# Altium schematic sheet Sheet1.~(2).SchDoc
size A4
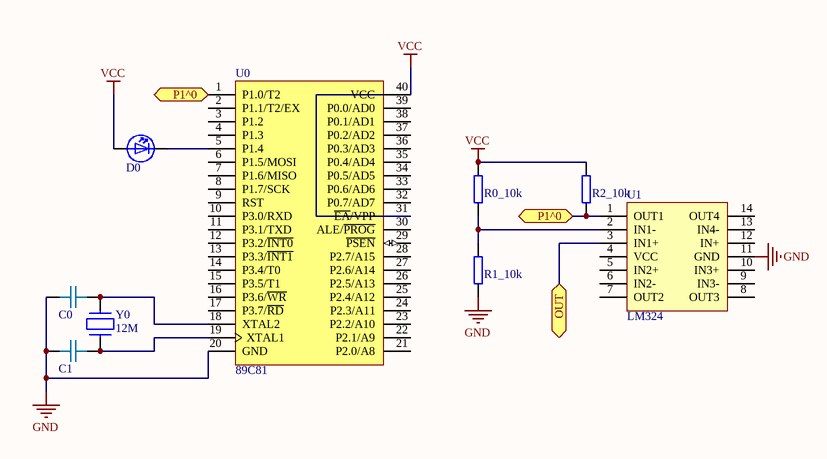
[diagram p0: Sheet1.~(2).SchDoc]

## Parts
C0  22pf  [capacitor-0.1]  (value not drawn)
C1  C_1  [capacitor-0.1]  (value not drawn)
D0  LED  [led-3]  (value not drawn)
R0_10k  RESIS  [resistor-0.4]  (value not drawn)
R1_10k  RESIS  [resistor-0.4]  (value not drawn)
R2_10k  RESIS  [resistor-0.4]  (value not drawn)
U0  89C81  [STC12C5A08S2]
U1  LM324  [DIP14]
Y0  XTAL  [Axial 0.2]  (value not drawn)

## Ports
OUT, P1^0

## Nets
GND: C0.1 C1.1 R1_10k.1 U0.20(GND) U1.11(GND)
VCC: D0.1 R0_10k.2 R2_10k.2 U0.40(VCC)
OUT: U1.3(IN1+) ; port OUT
P1^0: R2_10k.1 U0.1(P1.0/T2) U1.1(OUT1) ; port P1^0
NetC0_2: C0.2 U0.18(XTAL2) Y0.2
NetC1_2: C1.2 U0.19(XTAL1) Y0.1
NetD0_2: D0.2 U0.5(P1.4)
NetR0_10k_1: R0_10k.1 R1_10k.2 U1.2(IN1-)

Not connected (* = marked no-connect by the designer): U0 2(P1.1/T2/EX) 3(P1.2) 4(P1.3) 6(P1.5/MOSI) 7(P1.6/MISO) 8(P1.7/SCK) 9(RST) 10(P3.0/RXD) 11(P3.1/TXD) 12(P3.2/~{INT0}) 13(P3.3/~{INT1}) 14(P3.4/T0) 15(P3.5/T1) 16(P3.6/~{WR}) 17(P3.7/~{RD}) 21(P2.0/A8) 22(P2.1/A9) 23(P2.2/A10) 24(P2.3/A11) 25(P2.4/A12) 26(P2.5/A13) 27(P2.6/A14) 28(P2.7/A15) 29(~{PSEN}) 30(ALE/~{PROG}) 31(~{EA}/VPP) 32(P0.7/AD7) 33(P0.6/AD6) 34(P0.5/AD5) 35(P0.4/AD4) 36(P0.3/AD3) 37(P0.2/AD2) 38(P0.1/AD1) 39(P0.0/AD0); U1 4(VCC) 5(IN2+) 6(IN2-) 7(OUT2) 8(OUT3) 9(IN3-) 10(IN3+) 12(IN+) 13(IN4-) 14(OUT4)

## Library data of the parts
C0 = C_1
D0 = LED-30
U0 = STC12C5A08S2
